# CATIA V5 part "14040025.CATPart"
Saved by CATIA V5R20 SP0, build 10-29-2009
Part number: 14040025
Definition: NONE
Nomenclature: 14040025
Source: Unknown
Description: 14040025
Bounding box of the stored display mesh (mm): x -12.5 to 50, y -34 to 23.924, z -24.1 to 24.1
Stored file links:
  C:\Users\Utente\Desktop\IO LAVORO\3D X SITO CF\X SITO\PLASTICA\RF2\14040025.CATPart
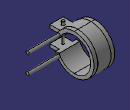
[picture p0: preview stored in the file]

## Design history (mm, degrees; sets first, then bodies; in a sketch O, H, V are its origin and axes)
Body1 "14040025" (main body)
  Solid1: solid without history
